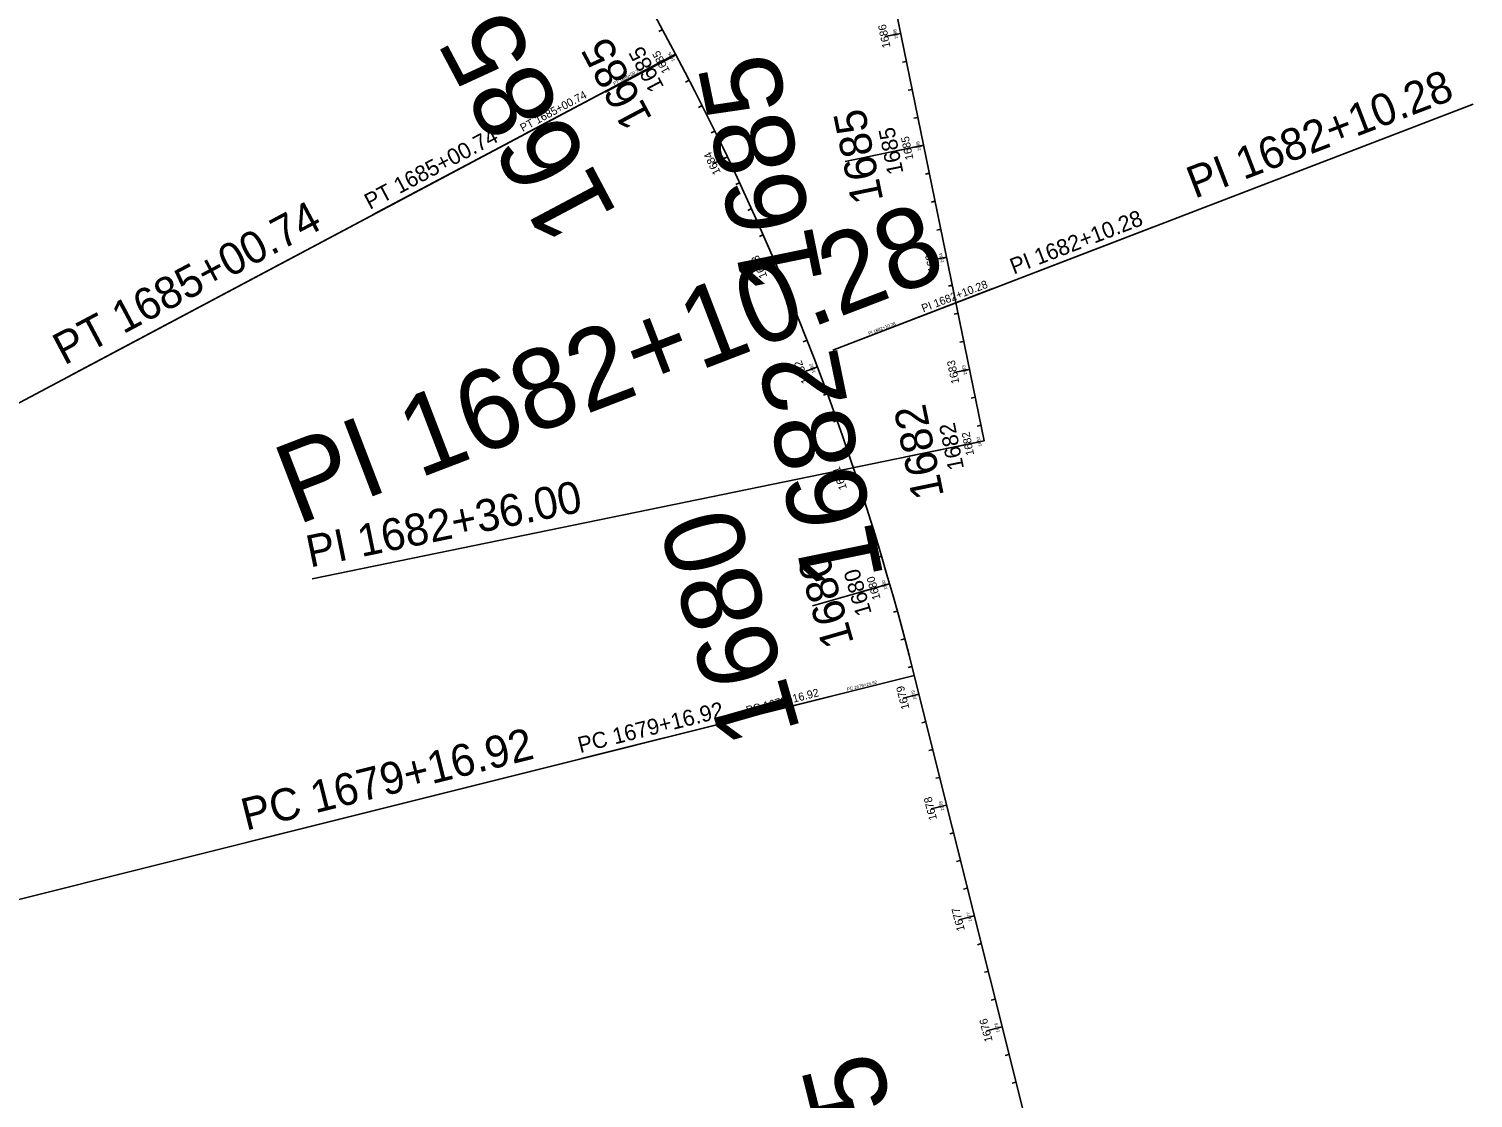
# Model space of a CAD drawing. Extents: x 353835 to 363333, y 126218 to 205387.
# Drawn here: x 361489 to 362752, y 126930 to 127866 of the extents above; entities that cross this region are included whole.
import ezdxf

# ---------------------------------------------------------------- set-up
doc = ezdxf.new("R2010")
doc.units = 0
for name, color, linetype in [('P_ALI_100_PIData', 7, 'Continuous'), ('P_ALI_100_Sta', 7, 'Continuous'), ('P_ALI_100_Tic', 7, 'Continuous'), ('P_ALI_20', 7, 'Continuous'), ('P_ALI_200_PIData', 7, 'Continuous'), ('P_ALI_200_Sta', 7, 'Continuous'), ('P_ALI_200_Tic', 7, 'Continuous'), ('P_ALI_20_PIData', 7, 'Continuous'), ('P_ALI_20_Sta', 7, 'Continuous'), ('P_ALI_20_Tic', 7, 'Continuous'), ('P_ALI_500_PIData', 7, 'Continuous'), ('P_ALI_500_Sta', 7, 'Continuous'), ('P_ALI_50_PIData', 7, 'Continuous'), ('P_ALI_50_Sta', 7, 'Continuous'), ('P_ALI_50_Tic', 7, 'Continuous')]:
    doc.layers.add(name, color=color, linetype=linetype)

msp = doc.modelspace()

# ---------------------------------------------------------------- linework, layer by layer
for points in [[(362251.3, 127861.8), (362251.3, 127861.8)], [(362291.5, 127665.9), (362291.5, 127665.9)], [(362311.6, 127567.9), (362311.6, 127567.9)]]:
    msp.add_lwpolyline(points)
at = {"layer": 'P_ALI_100_PIData'}
for points in [[(362054.4, 127843.7), (361789.5, 127703)], [(362054.4, 127843.7), (362001.4, 127815.6)], [(362192, 127584.7), (362472.1, 127692.2)], [(362192, 127584.7), (362248, 127606.2)], [(362263.2, 127300.1), (361972.2, 127227.3)], [(362263.2, 127300.1), (362205, 127285.5)]]:
    msp.add_lwpolyline(points, dxfattribs=at)
at = {"layer": 'P_ALI_100_Tic'}
for points in [[(362244.4, 127860.4), (362251.3, 127861.8)], [(361992.9, 127810.3), (362054.7, 127843.1)], [(362042.4, 127836.5), (362054.7, 127843.1)], [(362202.8, 127749.8), (362271.4, 127763.9)], [(362257.7, 127761), (362271.4, 127763.9)], [(362093.5, 127750.8), (362099.8, 127753.8)], [(362134.6, 127660), (362141.1, 127662.7)], [(362284.6, 127664.5), (362291.5, 127665.9)], [(362172, 127567.5), (362178.5, 127570)], [(362304.7, 127566.5), (362311.6, 127567.9)], [(362255.9, 127491.2), (362324.5, 127505.2)], [(362255.9, 127491.2), (362324.5, 127505.2)], [(362310.8, 127502.4), (362324.5, 127505.2)], [(362310.8, 127502.4), (362324.5, 127505.2)], [(362205.4, 127473.6), (362212.1, 127475.8)], [(362174.4, 127361), (362241.7, 127380.3)], [(362228.2, 127376.4), (362241.7, 127380.3)], [(362260.5, 127282), (362267.3, 127283.7)], [(362284.8, 127185), (362291.6, 127186.7)], [(362309.1, 127087.9), (362315.9, 127089.6)], [(362333.3, 126990.9), (362340.1, 126992.6)]]:
    msp.add_lwpolyline(points, dxfattribs=at)
at = {"layer": 'P_ALI_20'}
for p, q in [((362324.5, 127505.2), (361863.7, 129750.1)), ((362054.4, 127843.7), (361705.9, 128499.7)), ((362497.4, 126364), (362263.2, 127300.1))]:
    msp.add_line(p, q, dxfattribs=at)
msp.add_arc((359935, 126717.7), 2400, 14.0437, 27.9813, dxfattribs=at)
at = {"layer": 'P_ALI_200_PIData'}
for points in [[(362054.4, 127843.7), (361524.5, 127562.2)], [(362192, 127584.7), (362752.1, 127799.8)], [(362324.5, 127505.2), (361736.7, 127384.6)], [(362263.2, 127300.1), (361681.2, 127154.5)]]:
    msp.add_lwpolyline(points, dxfattribs=at)
at = {"layer": 'P_ALI_200_Tic'}
for points in [[(362237.6, 127859), (362251.3, 127861.8)], [(362030, 127830), (362054.7, 127843.1)], [(362244, 127758.2), (362271.4, 127763.9)], [(362087.1, 127747.8), (362099.8, 127753.8)], [(362128.2, 127657.2), (362141.1, 127662.7)], [(362277.8, 127663.1), (362291.5, 127665.9)], [(362165.4, 127565), (362178.5, 127570)], [(362297.9, 127565.1), (362311.6, 127567.9)], [(362297, 127499.6), (362324.5, 127505.2)], [(362297, 127499.6), (362324.5, 127505.2)], [(362198.8, 127471.4), (362212.1, 127475.8)], [(362214.8, 127372.6), (362241.7, 127380.3)], [(362253.7, 127280.3), (362267.3, 127283.7)], [(362278, 127183.3), (362291.6, 127186.7)], [(362302.3, 127086.2), (362315.9, 127089.6)], [(362326.5, 126989.2), (362340.1, 126992.6)]]:
    msp.add_lwpolyline(points, dxfattribs=at)
at = {"layer": 'P_ALI_20_Tic'}
for points in [[(362041.8, 127864.5), (362043, 127865.2)], [(362248.5, 127861.3), (362251.3, 127861.8)], [(362052.3, 127841.8), (362054.7, 127843.1)], [(362254.9, 127837), (362256.3, 127837.3)], [(362065.1, 127820.3), (362066.3, 127820.9)], [(362260, 127812.6), (362261.3, 127812.8)], [(362076.5, 127798), (362077.7, 127798.7)], [(362265, 127788.1), (362266.4, 127788.3)], [(362087.6, 127775.7), (362088.9, 127776.3)], [(362268.6, 127763.3), (362271.4, 127763.9)], [(362097.3, 127752.6), (362099.8, 127753.8)], [(362275, 127739.1), (362276.4, 127739.4)], [(362109.2, 127730.6), (362110.5, 127731.2)], [(362280.1, 127714.6), (362281.4, 127714.9)], [(362119.6, 127707.9), (362120.9, 127708.5)], [(362129.8, 127685.1), (362131.1, 127685.7)], [(362285.1, 127690.1), (362286.5, 127690.4)], [(362138.5, 127661.6), (362141.1, 127662.7)], [(362288.8, 127665.3), (362291.5, 127665.9)], [(362149.5, 127639.2), (362150.8, 127639.7)], [(362295.2, 127641.1), (362296.5, 127641.4)], [(362159, 127616), (362160.3, 127616.6)], [(362300.2, 127616.6), (362301.6, 127616.9)], [(362168.2, 127592.8), (362169.5, 127593.3)], [(362305.2, 127592.1), (362306.6, 127592.4)], [(362175.9, 127569), (362178.5, 127570)], [(362308.9, 127567.4), (362311.6, 127567.9)], [(362186, 127546.1), (362187.3, 127546.6)], [(362315.3, 127543.2), (362316.6, 127543.5)], [(362194.5, 127522.6), (362195.8, 127523.1)], [(362320.3, 127518.7), (362321.7, 127519)], [(362202.7, 127499), (362204, 127499.5)], [(362321.7, 127504.7), (362324.5, 127505.2)], [(362321.7, 127504.7), (362324.5, 127505.2)], [(362209.4, 127474.9), (362212.1, 127475.8)], [(362218.5, 127451.6), (362219.8, 127452.1)], [(362226, 127427.8), (362227.4, 127428.2)], [(362233.3, 127403.9), (362234.6, 127404.3)], [(362239, 127379.5), (362241.7, 127380.3)], [(362247.1, 127355.9), (362248.4, 127356.2)], [(362253.6, 127331.8), (362255, 127332.1)], [(362259.9, 127307.6), (362261.2, 127307.9)], [(362264.6, 127283), (362267.3, 127283.7)], [(362272, 127259.1), (362273.4, 127259.4)], [(362278.1, 127234.8), (362279.5, 127235.2)], [(362284.2, 127210.6), (362285.5, 127210.9)], [(362288.9, 127186), (362291.6, 127186.7)], [(362296.3, 127162.1), (362297.7, 127162.4)], [(362302.4, 127137.8), (362303.7, 127138.1)], [(362308.4, 127113.6), (362309.8, 127113.9)], [(362313.1, 127089), (362315.9, 127089.6)], [(362320.6, 127065.1), (362321.9, 127065.4)], [(362326.6, 127040.8), (362328, 127041.1)], [(362332.7, 127016.5), (362334.1, 127016.9)], [(362337.4, 126992), (362340.1, 126992.6)], [(362344.8, 126968), (362346.2, 126968.4)], [(362350.9, 126943.8), (362352.3, 126944.1)]]:
    msp.add_lwpolyline(points, dxfattribs=at)
at = {"layer": 'P_ALI_500_PIData'}
for points in [[(362054.4, 127843.7), (360729.7, 127140)], [(362192, 127584.7), (362332.1, 127638.5)], [(362263.2, 127300.1), (360808.1, 126936.1)]]:
    msp.add_lwpolyline(points, dxfattribs=at)
at = {"layer": 'P_ALI_50_PIData'}
for points in [[(362054.4, 127843.7), (361921.9, 127773.4)], [(362054.4, 127843.7), (361921.9, 127773.4)], [(362192, 127584.7), (362332.1, 127638.5)], [(362192, 127584.7), (362332.1, 127638.5)], [(362263.2, 127300.1), (362117.7, 127263.7)], [(362263.2, 127300.1), (362117.7, 127263.7)]]:
    msp.add_lwpolyline(points, dxfattribs=at)
at = {"layer": 'P_ALI_50_Tic'}
for points in [[(362039.9, 127863.5), (362043, 127865.2)], [(362039.9, 127863.5), (362043, 127865.2)], [(362244.4, 127860.4), (362251.3, 127861.8)], [(362048.6, 127839.8), (362054.7, 127843.1)], [(362048.6, 127839.8), (362054.7, 127843.1)], [(362252.9, 127836.6), (362256.3, 127837.3)], [(362063.2, 127819.3), (362066.3, 127820.9)], [(362063.2, 127819.3), (362066.3, 127820.9)], [(362257.9, 127812.1), (362261.3, 127812.8)], [(362074.6, 127797.1), (362077.7, 127798.7)], [(362074.6, 127797.1), (362077.7, 127798.7)], [(362262.9, 127787.6), (362266.4, 127788.3)], [(362085.7, 127774.8), (362088.9, 127776.3)], [(362085.7, 127774.8), (362088.9, 127776.3)], [(362264.5, 127762.4), (362271.4, 127763.9)], [(362093.5, 127750.8), (362099.8, 127753.8)], [(362093.5, 127750.8), (362099.8, 127753.8)], [(362273, 127738.7), (362276.4, 127739.4)], [(362107.3, 127729.7), (362110.5, 127731.2)], [(362107.3, 127729.7), (362110.5, 127731.2)], [(362278, 127714.2), (362281.4, 127714.9)], [(362117.7, 127707), (362120.9, 127708.5)], [(362117.7, 127707), (362120.9, 127708.5)], [(362127.9, 127684.2), (362131.1, 127685.7)], [(362127.9, 127684.2), (362131.1, 127685.7)], [(362283, 127689.7), (362286.5, 127690.4)], [(362134.6, 127660), (362141.1, 127662.7)], [(362134.6, 127660), (362141.1, 127662.7)], [(362284.6, 127664.5), (362291.5, 127665.9)], [(362147.6, 127638.4), (362150.8, 127639.7)], [(362147.6, 127638.4), (362150.8, 127639.7)], [(362293.1, 127640.7), (362296.5, 127641.4)], [(362157, 127615.3), (362160.3, 127616.6)], [(362157, 127615.3), (362160.3, 127616.6)], [(362298.1, 127616.2), (362301.6, 127616.9)], [(362166.2, 127592.1), (362169.5, 127593.3)], [(362166.2, 127592.1), (362169.5, 127593.3)], [(362303.1, 127591.7), (362306.6, 127592.4)], [(362172, 127567.5), (362178.5, 127570)], [(362172, 127567.5), (362178.5, 127570)], [(362304.7, 127566.5), (362311.6, 127567.9)], [(362184, 127545.4), (362187.3, 127546.6)], [(362184, 127545.4), (362187.3, 127546.6)], [(362313.2, 127542.7), (362316.6, 127543.5)], [(362192.5, 127521.9), (362195.8, 127523.1)], [(362192.5, 127521.9), (362195.8, 127523.1)], [(362318.2, 127518.3), (362321.7, 127519)], [(362200.7, 127498.4), (362204, 127499.5)], [(362200.7, 127498.4), (362204, 127499.5)], [(362317.6, 127503.8), (362324.5, 127505.2)], [(362317.6, 127503.8), (362324.5, 127505.2)], [(362205.4, 127473.6), (362212.1, 127475.8)], [(362205.4, 127473.6), (362212.1, 127475.8)], [(362216.5, 127451), (362219.8, 127452.1)], [(362216.5, 127451), (362219.8, 127452.1)], [(362224, 127427.2), (362227.4, 127428.2)], [(362224, 127427.2), (362227.4, 127428.2)], [(362231.3, 127403.3), (362234.6, 127404.3)], [(362231.3, 127403.3), (362234.6, 127404.3)], [(362234.9, 127378.4), (362241.7, 127380.3)], [(362234.9, 127378.4), (362241.7, 127380.3)], [(362245.1, 127355.3), (362248.4, 127356.2)], [(362245.1, 127355.3), (362248.4, 127356.2)], [(362251.6, 127331.2), (362255, 127332.1)], [(362251.6, 127331.2), (362255, 127332.1)], [(362257.9, 127307.1), (362261.2, 127307.9)], [(362257.9, 127307.1), (362261.2, 127307.9)], [(362260.5, 127282), (362267.3, 127283.7)], [(362260.5, 127282), (362267.3, 127283.7)], [(362270, 127258.6), (362273.4, 127259.4)], [(362270, 127258.6), (362273.4, 127259.4)], [(362276.1, 127234.3), (362279.5, 127235.2)], [(362276.1, 127234.3), (362279.5, 127235.2)], [(362282.1, 127210.1), (362285.5, 127210.9)], [(362282.1, 127210.1), (362285.5, 127210.9)], [(362284.8, 127185), (362291.6, 127186.7)], [(362284.8, 127185), (362291.6, 127186.7)], [(362294.3, 127161.6), (362297.7, 127162.4)], [(362294.3, 127161.6), (362297.7, 127162.4)], [(362300.3, 127137.3), (362303.7, 127138.1)], [(362300.3, 127137.3), (362303.7, 127138.1)], [(362306.4, 127113), (362309.8, 127113.9)], [(362306.4, 127113), (362309.8, 127113.9)], [(362309.1, 127087.9), (362315.9, 127089.6)], [(362309.1, 127087.9), (362315.9, 127089.6)], [(362318.5, 127064.5), (362321.9, 127065.4)], [(362318.5, 127064.5), (362321.9, 127065.4)], [(362324.6, 127040.3), (362328, 127041.1)], [(362324.6, 127040.3), (362328, 127041.1)], [(362330.7, 127016), (362334.1, 127016.9)], [(362330.7, 127016), (362334.1, 127016.9)], [(362333.3, 126990.9), (362340.1, 126992.6)], [(362333.3, 126990.9), (362340.1, 126992.6)], [(362342.8, 126967.5), (362346.2, 126968.4)], [(362342.8, 126967.5), (362346.2, 126968.4)], [(362348.9, 126943.3), (362352.3, 126944.1)], [(362348.9, 126943.3), (362352.3, 126944.1)]]:
    msp.add_lwpolyline(points, dxfattribs=at)

# ---------------------------------------------------------------- texts
at = {"layer": 'P_ALI_100_PIData'}
for s, rotation, p in [('PT 1685+00.74', 27.9813, (361787.1, 127707.4)), ('PI 1682+10.28', 21.0125, (362350.3, 127650.8)), ('PC 1679+16.92', 14.0437, (361971, 127232.1))]:
    msp.add_text(s, height=14, rotation=rotation, dxfattribs=at).set_placement(p)
at = {"layer": 'P_ALI_100_Sta'}
for s, rotation, p in [('1685', 117.9637, (362044.7, 127815.1)), ('1685', 101.6001, (362253.9, 127739.9)), ('1682', 101.6001, (362306.9, 127481.3)), ('1682', 101.6001, (362306.9, 127481.3)), ('1680', 106.0271, (362226.2, 127354.5))]:
    msp.add_text(s, height=14, rotation=rotation, dxfattribs=at).set_placement(p)
at = {"layer": 'P_ALI_200_PIData'}
for s, rotation, p in [('PI 1682+10.28', 21.0125, (362508.6, 127717)), ('PT 1685+00.74', 27.9813, (361519.8, 127571.1)), ('PI 1682+36.00', 11.6001, (361734.7, 127394.4)), ('PC 1679+16.92', 14.0437, (361678.7, 127164.2))]:
    msp.add_text(s, height=28, rotation=rotation, dxfattribs=at).set_placement(p)
at = {"layer": 'P_ALI_200_Sta'}
for s, rotation, p in [('1685', 117.9637, (362034.6, 127787.2)), ('1685', 101.6001, (362236.3, 127715.9)), ('1682', 101.6001, (362289.4, 127457.3)), ('1682', 101.6001, (362289.4, 127457.3)), ('1680', 106.0271, (362210.7, 127328.7))]:
    msp.add_text(s, height=28, rotation=rotation, dxfattribs=at).set_placement(p)
at = {"layer": 'P_ALI_20_PIData'}
for s, rotation, p in [('PT 1685+00.74', 27.9813, (362000.9, 127816.5)), ('PI 1682+10.28', 21.0125, (362223.7, 127597.9)), ('PC 1679+16.92', 14.0437, (362204.8, 127286.5))]:
    msp.add_text(s, height=2.8, rotation=rotation, dxfattribs=at).set_placement(p)
at = {"layer": 'P_ALI_20_Sta'}
for s, rotation, p in [('1686', 101.6001, (362249.1, 127857.3)), ('1685', 117.9637, (362053.9, 127838.1)), ('1685', 101.6001, (362269.2, 127759.3)), ('1684', 115.5764, (362098.7, 127748.9)), ('1683', 113.189, (362139.8, 127657.8)), ('1684', 101.6001, (362289.3, 127661.4)), ('1682', 110.8017, (362177, 127565.2)), ('1683', 101.6001, (362309.4, 127563.4)), ('1682', 101.6001, (362322.3, 127500.7)), ('1682', 101.6001, (362322.3, 127500.7)), ('1681', 108.4144, (362210.3, 127471.4)), ('1680', 106.0271, (362239.8, 127375.5)), ('1679', 104.0437, (362265.3, 127279)), ('1678', 104.0437, (362289.6, 127182)), ('1677', 104.0437, (362313.8, 127085)), ('1676', 104.0437, (362338.1, 126988))]:
    msp.add_text(s, height=2.8, rotation=rotation, dxfattribs=at).set_placement(p)
at = {"layer": 'P_ALI_500_PIData'}
msp.add_text('PI 1682+10.28', height=70, rotation=21.0125, dxfattribs=at).set_placement((361723.2, 127431.3))
at = {"layer": 'P_ALI_500_Sta'}
for s, rotation, p in [('1685', 117.9637, (362004.4, 127703.4)), ('1685', 101.6001, (362183.7, 127644)), ('1682', 101.6001, (362236.8, 127385.4)), ('1682', 101.6001, (362236.8, 127385.4)), ('1680', 106.0271, (362164.2, 127251.4)), ('1675', 104.0437, (362281.9, 126772.1))]:
    msp.add_text(s, height=70, rotation=rotation, dxfattribs=at).set_placement(p)
at = {"layer": 'P_ALI_50_PIData'}
for s, rotation, p in [('PT 1685+00.74', 27.9813, (361920.8, 127775.6)), ('PT 1685+00.74', 27.9813, (361920.8, 127775.6)), ('PI 1682+10.28', 21.0125, (362271.2, 127617.7)), ('PI 1682+10.28', 21.0125, (362271.2, 127617.7)), ('PC 1679+16.92', 14.0437, (362117.1, 127266.1)), ('PC 1679+16.92', 14.0437, (362117.1, 127266.1))]:
    msp.add_text(s, height=7, rotation=rotation, dxfattribs=at).set_placement(p)
at = {"layer": 'P_ALI_50_Sta'}
for s, rotation, p in [('1686', 101.6001, (362242.5, 127849.9)), ('1685', 117.9637, (362049.7, 127829.1)), ('1685', 117.9637, (362049.7, 127829.1)), ('1685', 101.6001, (362262.6, 127751.9)), ('1684', 115.5764, (362094.2, 127740.1)), ('1684', 115.5764, (362094.2, 127740.1)), ('1684', 101.6001, (362282.7, 127653.9)), ('1683', 113.189, (362134.9, 127649.2)), ('1683', 113.189, (362134.9, 127649.2)), ('1682', 110.8017, (362171.8, 127556.8)), ('1682', 110.8017, (362171.8, 127556.8)), ('1683', 101.6001, (362302.8, 127556)), ('1682', 101.6001, (362315.7, 127493.3)), ('1682', 101.6001, (362315.7, 127493.3)), ('1681', 108.4144, (362204.5, 127463.7)), ('1681', 108.4144, (362204.5, 127463.7)), ('1680', 106.0271, (362233.9, 127367.4)), ('1680', 106.0271, (362233.9, 127367.4)), ('1679', 104.0437, (362259.1, 127271.3)), ('1679', 104.0437, (362259.1, 127271.3)), ('1678', 104.0437, (362283.3, 127174.3)), ('1678', 104.0437, (362283.3, 127174.3)), ('1677', 104.0437, (362307.6, 127077.3)), ('1677', 104.0437, (362307.6, 127077.3)), ('1676', 104.0437, (362331.9, 126980.3)), ('1676', 104.0437, (362331.9, 126980.3))]:
    msp.add_text(s, height=7, rotation=rotation, dxfattribs=at).set_placement(p)

doc.saveas('drawing.dxf')
